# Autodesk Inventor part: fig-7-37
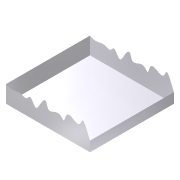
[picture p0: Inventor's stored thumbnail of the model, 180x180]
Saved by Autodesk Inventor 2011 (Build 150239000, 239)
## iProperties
Shininess: 64.0
Length Units: 11269
Angle Units: 11279
Time Units: 11290
Mass Units: 11283
Length Display Precision: 3
Angle Display Precision: 2
Compacted: True
Part Number: fig-7-37
Document SubType Name: Modeling
Created: 2002-12
Designer: deepak
Density: 1 g/cm^3
Density: 0.0
Volumn: 0.0
Area: 0.0
PropertySet Name: Model Information
Control State: 0
Master: False
Checked Out: False
Author: deepak
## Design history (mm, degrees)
sketch "Sketch1"
  geometry: L1 (-32.188, 30.089)-(27.812, 30.089); L2 (27.812, 30.089)-(27.812, -29.911); L3 (27.812, -29.911)-(-32.188, -29.911); L4 (-32.188, -29.911)-(-32.188, 30.089)
  constraints: 8 end point, 2 parallel, 1 horizontal, 1 perpendicular
  dimensions: "d0" = 60 distance of L1.start L1.end; "d1" = 60 distance of L3.end L1.start
extrude "Extrusion1" new body sketch "Sketch1" stored distance "d2" = 20; taper "d3" = 0 deg
sketch "Sketch2"
  geometry: 17 further points
  constraints: 17 other
extrude_surface "ExtrusionSrf1" sketch "Sketch2" dims "d4" = 70, "d5" = 0
split "Split1"
delete_face "Delete Face1"
node "Sketch5"
body "Srf1"
body "Srf2"
